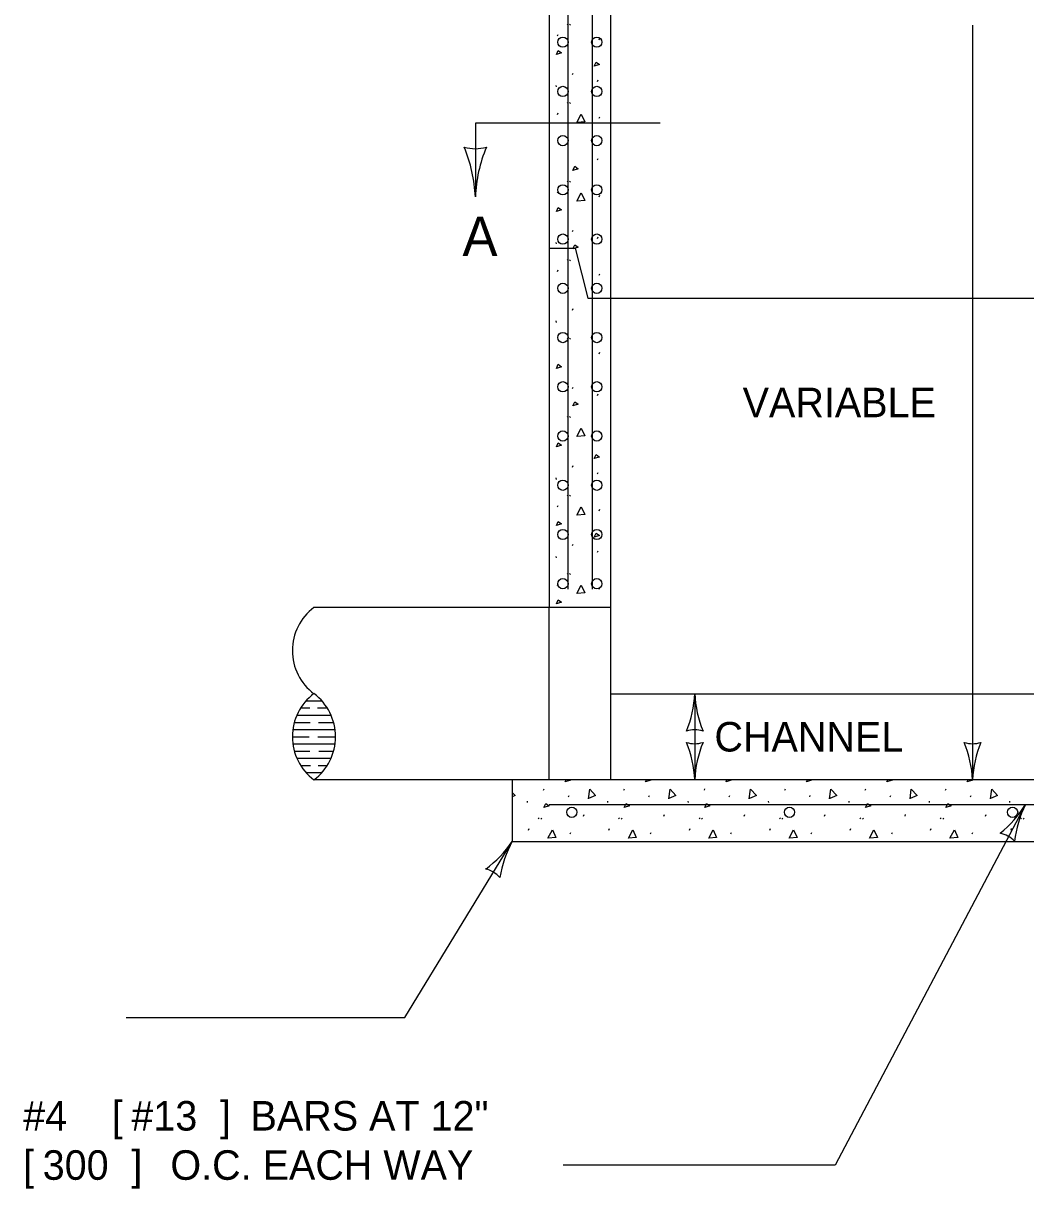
# Model space of a CAD drawing. Extents: x 49991.4 to 50028.3, y 49987.6 to 50011.4.
# Drawn here: x 50024.846 to 50026.881, y 49988.597 to 49990.964 of the extents above; entities that cross this region are included whole.
import ezdxf

# ---------------------------------------------------------------- set-up
doc = ezdxf.new("R2010")
doc.units = 0
for name, color, linetype in [('Level 1', 7, 'Continuous'), ('Level 2', 7, 'Continuous'), ('Level 3', 7, 'Continuous'), ('Level 4', 7, 'Continuous'), ('Level 6', 7, 'Continuous')]:
    doc.layers.add(name, color=color, linetype=linetype)

msp = doc.modelspace()

# ---------------------------------------------------------------- linework, layer by layer
at = {"layer": 'Level 1'}
for p, q in [((50025.9134, 49991.4777), (50025.9134, 49989.7777)), ((50025.9509, 49991.4401), (50025.9509, 49989.8151)), ((50026.0009, 49991.4401), (50026.0009, 49989.8151)), ((50025.9302, 49990.9388), (50025.9315, 49990.9418)), ((50025.9499, 49990.9635), (50025.9512, 49990.9615)), ((50025.9549, 49990.9627), (50025.9563, 49990.9607)), ((50026.0146, 49990.9311), (50026.0159, 49990.9341)), ((50025.9606, 49990.8602), (50025.9619, 49990.8632)), ((50026.0113, 49990.8465), (50026.0126, 49990.8495)), ((50025.9271, 49990.8381), (50025.9275, 49990.8352)), ((50025.9499, 49990.804), (50025.9512, 49990.802)), ((50025.9549, 49990.8033), (50025.9563, 49990.8013)), ((50025.9302, 49990.7793), (50025.9315, 49990.7823)), ((50026.0146, 49990.7717), (50026.0159, 49990.7747)), ((50026.0113, 49990.6871), (50026.0126, 49990.6901)), ((50025.9499, 49990.6445), (50025.9512, 49990.6425)), ((50025.9549, 49990.6438), (50025.9563, 49990.6418)), ((50025.9302, 49990.6199), (50025.9315, 49990.6229)), ((50026.0146, 49990.6122), (50026.0159, 49990.6152)), ((50025.9606, 49990.5413), (50025.9619, 49990.5443)), ((50025.9271, 49990.5193), (50025.9275, 49990.5163)), ((50026.0113, 49990.5276), (50026.0126, 49990.5306)), ((50025.9134, 49990.5077), (50025.9663, 49990.5077)), ((50025.9663, 49990.5077), (50025.9916, 49990.4059)), ((50025.9499, 49990.4851), (50025.9512, 49990.4831)), ((50025.9549, 49990.4843), (50025.9563, 49990.4823)), ((50025.9302, 49990.4604), (50025.9315, 49990.4634)), ((50026.0146, 49990.4527), (50026.0159, 49990.4557)), ((50025.9916, 49990.4059), (50027.2602, 49990.4059)), ((50025.9606, 49990.3818), (50025.9619, 49990.3848)), ((50025.9271, 49990.3598), (50025.9275, 49990.3568)), ((50025.9499, 49990.3256), (50025.9512, 49990.3236)), ((50025.9549, 49990.3249), (50025.9563, 49990.3229)), ((50026.0146, 49990.2933), (50026.0159, 49990.2963)), ((50025.9606, 49990.2223), (50025.9619, 49990.2253)), ((50026.0113, 49990.2087), (50026.0126, 49990.2117)), ((50025.9499, 49990.1662), (50025.9512, 49990.1642)), ((50025.9549, 49990.1654), (50025.9563, 49990.1634)), ((50026.0146, 49990.1338), (50026.0159, 49990.1368)), ((50025.9606, 49990.0629), (50025.9619, 49990.0659)), ((50026.0113, 49990.0493), (50026.0126, 49990.0523)), ((50025.9271, 49990.0409), (50025.9275, 49990.0379)), ((50025.9499, 49990.0067), (50025.9512, 49990.0047)), ((50025.9549, 49990.0059), (50025.9563, 49990.0039)), ((50025.9302, 49989.982), (50025.9315, 49989.985)), ((50026.0146, 49989.9744), (50026.0159, 49989.9774)), ((50025.9606, 49989.9035), (50025.9619, 49989.9065)), ((50025.9271, 49989.8814), (50025.9275, 49989.8784)), ((50026.0113, 49989.8898), (50026.0126, 49989.8928)), ((50025.9499, 49989.8473), (50025.9512, 49989.8453)), ((50025.9549, 49989.8465), (50025.9563, 49989.8445)), ((50025.9302, 49989.8226), (50025.9315, 49989.8256)), ((50026.0146, 49989.8149), (50026.0159, 49989.8179)), ((50026.0384, 49989.7777), (50025.4357, 49989.7777)), ((50026.0384, 49989.6027), (50027.2134, 49989.6027)), ((50025.4088, 49989.5736), (50025.4271, 49989.5736)), ((50025.4198, 49989.5882), (50025.4516, 49989.5882)), ((50025.4428, 49989.5736), (50025.4626, 49989.5736)), ((50025.3959, 49989.5444), (50025.4278, 49989.5444)), ((50025.4011, 49989.559), (50025.4703, 49989.559)), ((50025.4451, 49989.5444), (50025.4754, 49989.5444)), ((50025.3929, 49989.5298), (50025.4784, 49989.5298)), ((50025.3919, 49989.5152), (50025.4263, 49989.5152)), ((50025.3929, 49989.5007), (50025.4784, 49989.5007)), ((50025.4435, 49989.5152), (50025.4794, 49989.5152)), ((50025.3959, 49989.4861), (50025.4271, 49989.4861)), ((50025.4458, 49989.4861), (50025.4754, 49989.4861)), ((50025.4011, 49989.4715), (50025.4703, 49989.4715)), ((50025.4088, 49989.4569), (50025.4285, 49989.4569)), ((50025.4442, 49989.4569), (50025.4626, 49989.4569)), ((50025.4198, 49989.4423), (50025.4516, 49989.4423)), ((50026.0384, 49989.4277), (50025.4357, 49989.4277)), ((50025.8384, 49989.4277), (50025.8384, 49989.3027)), ((50025.9019, 49989.4064), (50025.9032, 49989.4094)), ((50026.0651, 49989.4064), (50026.0665, 49989.4094)), ((50026.2284, 49989.4064), (50026.2297, 49989.4094)), ((50026.3917, 49989.4064), (50026.393, 49989.4094)), ((50026.5549, 49989.4064), (50026.5563, 49989.4094)), ((50026.7182, 49989.4064), (50026.7195, 49989.4094)), ((50025.8684, 49989.3844), (50025.8687, 49989.3814)), ((50025.9525, 49989.3928), (50025.9538, 49989.3958)), ((50026.0317, 49989.3844), (50026.032, 49989.3814)), ((50026.1157, 49989.3928), (50026.1171, 49989.3958)), ((50026.1949, 49989.3844), (50026.1953, 49989.3814)), ((50026.279, 49989.3928), (50026.2803, 49989.3958)), ((50026.3582, 49989.3844), (50026.3585, 49989.3814)), ((50026.4423, 49989.3928), (50026.4436, 49989.3958)), ((50026.5215, 49989.3844), (50026.5218, 49989.3814)), ((50026.6055, 49989.3928), (50026.6069, 49989.3958)), ((50026.6847, 49989.3844), (50026.6851, 49989.3814)), ((50026.7688, 49989.3928), (50026.7701, 49989.3958)), ((50026.848, 49989.3844), (50026.8483, 49989.3814)), ((50025.9134, 49989.3777), (50027.3384, 49989.3777)), ((50025.9828, 49989.3541), (50025.9841, 49989.3571)), ((50026.1461, 49989.3541), (50026.1474, 49989.3571)), ((50026.3093, 49989.3541), (50026.3107, 49989.3571)), ((50026.4726, 49989.3541), (50026.4739, 49989.3571)), ((50026.6359, 49989.3541), (50026.6372, 49989.3571)), ((50026.7991, 49989.3541), (50026.8005, 49989.3571)), ((50025.8911, 49989.3503), (50025.8925, 49989.3483)), ((50025.8962, 49989.3495), (50025.8975, 49989.3475)), ((50026.0544, 49989.3503), (50026.0557, 49989.3483)), ((50026.0595, 49989.3495), (50026.0608, 49989.3475)), ((50026.2177, 49989.3503), (50026.219, 49989.3483)), ((50026.2227, 49989.3495), (50026.2241, 49989.3475)), ((50026.3809, 49989.3503), (50026.3823, 49989.3483)), ((50026.386, 49989.3495), (50026.3873, 49989.3475)), ((50026.5442, 49989.3503), (50026.5455, 49989.3483)), ((50026.5493, 49989.3495), (50026.5506, 49989.3475)), ((50026.7075, 49989.3503), (50026.7088, 49989.3483)), ((50026.7125, 49989.3495), (50026.7139, 49989.3475)), ((50026.8707, 49989.3503), (50026.8721, 49989.3483)), ((50026.8758, 49989.3495), (50026.8771, 49989.3475)), ((50025.8715, 49989.3256), (50025.8728, 49989.3285)), ((50025.9558, 49989.3179), (50025.9571, 49989.3209)), ((50026.0347, 49989.3256), (50026.0361, 49989.3285)), ((50026.1191, 49989.3179), (50026.1204, 49989.3209)), ((50026.198, 49989.3256), (50026.1993, 49989.3285)), ((50026.2823, 49989.3179), (50026.2837, 49989.3209)), ((50026.3613, 49989.3256), (50026.3626, 49989.3285)), ((50026.4456, 49989.3179), (50026.4469, 49989.3209)), ((50026.5245, 49989.3256), (50026.5259, 49989.3285)), ((50026.6089, 49989.3179), (50026.6102, 49989.3209)), ((50026.6878, 49989.3256), (50026.6891, 49989.3285)), ((50026.7721, 49989.3179), (50026.7735, 49989.3209)), ((50026.8511, 49989.3256), (50026.8524, 49989.3285)), ((50025.8384, 49989.3027), (50027.4134, 49989.3027))]:
    msp.add_line(p, q, dxfattribs=at)
msp.add_lwpolyline([(50026.0384, 49991.4777), (50027.2134, 49991.4777), (50027.2134, 49989.4277), (50026.0384, 49989.4277)], close=True, dxfattribs=at)
for points in [[(50025.9279, 49990.9011), (50025.9319, 49990.9095), (50025.9385, 49990.9045), (50025.9279, 49990.9011)], [(50026.0047, 49990.8773), (50026.0087, 49990.8857), (50026.0153, 49990.8807), (50026.0047, 49990.8773)], [(50025.9696, 49990.7627), (50025.9786, 49990.7797), (50025.9856, 49990.764), (50025.9699, 49990.7627)], [(50025.9613, 49990.6657), (50025.9653, 49990.6741), (50025.9719, 49990.6691), (50025.9613, 49990.6657)], [(50025.9696, 49990.6032), (50025.9786, 49990.6202), (50025.9856, 49990.6045), (50025.9699, 49990.6032)], [(50025.9279, 49990.5822), (50025.9319, 49990.5905), (50025.9385, 49990.5855), (50025.9279, 49990.5822)], [(50025.9613, 49990.5063), (50025.9653, 49990.5146), (50025.9719, 49990.5096), (50025.9613, 49990.5063)], [(50025.9279, 49990.2633), (50025.9319, 49990.2717), (50025.9385, 49990.2667), (50025.9279, 49990.2633)], [(50025.9613, 49990.1874), (50025.9653, 49990.1957), (50025.9719, 49990.1907), (50025.9613, 49990.1874)], [(50025.9696, 49990.1249), (50025.9786, 49990.1418), (50025.9856, 49990.1262), (50025.9699, 49990.1249)], [(50025.9279, 49990.1039), (50025.9319, 49990.1122), (50025.9385, 49990.1072), (50025.9279, 49990.1039)], [(50026.0047, 49990.0801), (50026.0087, 49990.0884), (50026.0153, 49990.0834), (50026.0047, 49990.0801)], [(50025.9696, 49989.9654), (50025.9786, 49989.9824), (50025.9856, 49989.9667), (50025.9699, 49989.9654)], [(50025.9279, 49989.9444), (50025.9319, 49989.9527), (50025.9385, 49989.9477), (50025.9279, 49989.9444)], [(50026.0047, 49989.9206), (50026.0087, 49989.9289), (50026.0153, 49989.9239), (50026.0047, 49989.9206)], [(50025.9696, 49989.8059), (50025.9786, 49989.8229), (50025.9856, 49989.8073), (50025.9699, 49989.8059)], [(50025.9279, 49989.7849), (50025.9319, 49989.7933), (50025.9385, 49989.7883), (50025.9279, 49989.7849)], [(50025.9459, 49989.4236), (50025.9478, 49989.4277)], [(50025.9556, 49989.4277), (50025.9565, 49989.4269), (50025.9459, 49989.4236)], [(50026.1091, 49989.4236), (50026.1111, 49989.4277)], [(50026.1188, 49989.4277), (50026.1198, 49989.4269), (50026.1091, 49989.4236)], [(50026.2724, 49989.4236), (50026.2744, 49989.4277)], [(50026.2821, 49989.4277), (50026.2831, 49989.4269), (50026.2724, 49989.4236)], [(50026.4357, 49989.4236), (50026.4376, 49989.4277)], [(50026.4454, 49989.4277), (50026.4463, 49989.4269), (50026.4357, 49989.4236)], [(50026.5989, 49989.4236), (50026.6009, 49989.4277)], [(50026.6086, 49989.4277), (50026.6096, 49989.4269), (50026.5989, 49989.4236)], [(50026.7622, 49989.4236), (50026.7642, 49989.4277)], [(50026.7719, 49989.4277), (50026.7729, 49989.4269), (50026.7622, 49989.4236)], [(50025.8384, 49989.4021), (50025.8443, 49989.3961), (50025.8384, 49989.3933)], [(50025.993, 49989.3893), (50025.9956, 49989.4084), (50026.0075, 49989.3961), (50025.9933, 49989.3895)], [(50026.1563, 49989.3893), (50026.1589, 49989.4084), (50026.1708, 49989.3961), (50026.1566, 49989.3895)], [(50026.3195, 49989.3893), (50026.3222, 49989.4084), (50026.3341, 49989.3961), (50026.3199, 49989.3895)], [(50026.4828, 49989.3893), (50026.4854, 49989.4084), (50026.4973, 49989.3961), (50026.4831, 49989.3895)], [(50026.6461, 49989.3893), (50026.6487, 49989.4084), (50026.6606, 49989.3961), (50026.6464, 49989.3895)], [(50026.8093, 49989.3893), (50026.8119, 49989.4084), (50026.8239, 49989.3961), (50026.8096, 49989.3895)], [(50025.9025, 49989.3715), (50025.9065, 49989.3798), (50025.9132, 49989.3748), (50025.9025, 49989.3715)], [(50026.0658, 49989.3715), (50026.0698, 49989.3798), (50026.0765, 49989.3748), (50026.0658, 49989.3715)], [(50026.2291, 49989.3715), (50026.2331, 49989.3798), (50026.2397, 49989.3748), (50026.2291, 49989.3715)], [(50026.5556, 49989.3715), (50026.5596, 49989.3798), (50026.5663, 49989.3748), (50026.5556, 49989.3715)], [(50026.7189, 49989.3715), (50026.7229, 49989.3798), (50026.7295, 49989.3748), (50026.7189, 49989.3715)], [(50025.9109, 49989.3089), (50025.9199, 49989.3259), (50025.9269, 49989.3103), (50025.9112, 49989.3089)], [(50026.0741, 49989.3089), (50026.0831, 49989.3259), (50026.0901, 49989.3103), (50026.0745, 49989.3089)], [(50026.2374, 49989.3089), (50026.2464, 49989.3259), (50026.2534, 49989.3103), (50026.2377, 49989.3089)], [(50026.4007, 49989.3089), (50026.4097, 49989.3259), (50026.4166, 49989.3103), (50026.401, 49989.3089)], [(50026.5639, 49989.3089), (50026.5729, 49989.3259), (50026.5799, 49989.3103), (50026.5643, 49989.3089)], [(50026.7272, 49989.3089), (50026.7362, 49989.3259), (50026.7432, 49989.3103), (50026.7275, 49989.3089)]]:
    msp.add_lwpolyline(points, dxfattribs=at)
for centre in [(50025.9413, 49990.9261), (50026.01, 49990.9261), (50025.9413, 49990.8261), (50026.01, 49990.8261), (50025.9413, 49990.7261), (50026.01, 49990.7261), (50025.9413, 49990.6261), (50026.01, 49990.6261), (50025.9413, 49990.5261), (50026.01, 49990.5261), (50025.9413, 49990.4261), (50026.01, 49990.4261), (50025.9413, 49990.3261), (50026.01, 49990.3261), (50025.9413, 49990.2261), (50026.01, 49990.2261), (50025.9413, 49990.1261), (50026.01, 49990.1261), (50025.9413, 49990.0261), (50026.01, 49990.0261), (50025.9413, 49989.9261), (50026.01, 49989.9261), (50025.9413, 49989.8261), (50026.01, 49989.8261), (50025.9594, 49989.3617), (50026.4014, 49989.3617), (50026.8543, 49989.3617)]:
    msp.add_circle(centre, 0.0104, dxfattribs=at)
for centre, start, end in [((50025.5013, 49989.6902), 126.8699, 233.1301), ((50025.5013, 49989.5152), 126.8699, 233.1301), ((50025.3701, 49989.5152), 306.8699, 53.1301)]:
    msp.add_arc(centre, 0.1094, start, end, dxfattribs=at)
at = {"layer": 'Level 3'}
for p, q in [((50026.773, 49990.9607), (50026.773, 49989.4277)), ((50026.2089, 49989.6027), (50026.2089, 49989.4277)), ((50026.8803, 49989.3777), (50026.4941, 49988.6452)), ((50025.62, 49988.9452), (50025.8384, 49989.3027)), ((50025.0547, 49988.9452), (50025.62, 49988.9452)), ((50026.4941, 49988.6452), (50025.942, 49988.6452))]:
    msp.add_line(p, q, dxfattribs=at)
for centre, radius, start, end in [((50025.7634, 49990.7826), 0.073, 252.1388, 287.8612), ((50025.4531, 49990.5963), 0.3107, 2.8273, 22.0772), ((50026.0595, 49990.5994), 0.2964, 157.456, 177.6395), ((50025.9868, 49989.6119), 0.2223, 337.456, 357.6395), ((50026.4416, 49989.6142), 0.233, 182.8273, 202.0772), ((50026.2089, 49989.4745), 0.0548, 72.1388, 107.8612), ((50026.2089, 49989.5559), 0.0548, 252.1388, 287.8612), ((50025.9762, 49989.4162), 0.233, 2.8273, 22.0772), ((50026.431, 49989.4186), 0.2223, 157.456, 177.6395), ((50026.773, 49989.5559), 0.0548, 252.1388, 287.8612), ((50026.5403, 49989.4162), 0.233, 2.8273, 22.0772), ((50026.9952, 49989.4186), 0.2223, 157.456, 177.6395), ((50026.6901, 49989.4928), 0.2223, 308.6595, 328.843), ((50027.0898, 49989.2757), 0.233, 154.0308, 173.2806), ((50026.8186, 49989.2654), 0.0548, 43.3423, 79.0646), ((50025.6536, 49989.4263), 0.2223, 306.0359, 326.2194), ((50026.043, 49989.1912), 0.233, 151.4072, 170.657), ((50025.7715, 49989.1933), 0.0548, 40.7187, 76.441)]:
    msp.add_arc(centre, radius, start, end, dxfattribs=at)
at = {"layer": 'Level 4'}
msp.add_line((50025.9134, 49989.4277), (50025.9134, 49989.7777), dxfattribs=at)
at = {"layer": 'Level 6'}
for p, q in [((50026.1384, 49990.7617), (50025.7634, 49990.7617)), ((50025.7634, 49990.7617), (50025.7634, 49990.6117))]:
    msp.add_line(p, q, dxfattribs=at)

# ---------------------------------------------------------------- texts
at = {"layer": 'Level 2'}
for s, height, p in [('A', 0.0799, (50025.7372, 49990.4918)), ('VARIABLE', 0.06, (50026.3062, 49990.1642)), ('CHANNEL', 0.06, (50026.2489, 49989.4852)), ('#4 ', 0.06, (50024.8452, 49988.7152)), ('[', 0.06, (50025.0252, 49988.7152)), ('#13', 0.06, (50025.0649, 49988.7152)), (']', 0.06, (50025.2449, 49988.7152)), (' BARS AT 12"', 0.06, (50025.2846, 49988.7152)), ('[', 0.06, (50024.8452, 49988.6152)), ('300', 0.06, (50024.8849, 49988.6152)), ('] ', 0.06, (50025.0649, 49988.6152)), ('O.C. EACH WAY', 0.06, (50025.1442, 49988.6152))]:
    msp.add_text(s, height=height, dxfattribs=at).set_placement(p)

doc.saveas('drawing.dxf')
